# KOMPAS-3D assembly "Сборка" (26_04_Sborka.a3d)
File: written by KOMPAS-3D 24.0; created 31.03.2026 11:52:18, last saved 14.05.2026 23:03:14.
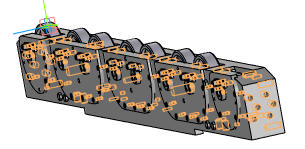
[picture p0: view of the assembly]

Document properties: Автор: taras; Полное имя файла: E:\test_kompas\all_v22\26_04_Sborka.a3d

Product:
- Component [detail]: Деталь  | qty 1  | pos. 2  | Масса: 261.985445; source file: C:\Users\Family\Desktop\kommpas\3.1.8 дет.45 Балка(оригинал) (1).m3d
- Component [detail]: Деталь  | qty 1  | pos. 3  | Масса: 21.934157; Организация: TMK; Автор: TMK; source file: C:\Users\Family\Desktop\kommpas\3.1.8  дет.46.2 Крышка балки (2).m3d
- Component [detail]: Деталь  | qty 1  | pos. 4  | Масса: 21.934157; Организация: TMK; Автор: TMK; source file: C:\Users\Family\Desktop\kommpas\3.1.8  дет.46.2 Крышка балки (2).m3d
- Component [detail]: Деталь  | qty 1  | pos. 5  | Масса: 9.688835; source file: C:\Users\Family\Desktop\kommpas\Крышка балки 1 окончательная (3).m3d
- Component [detail]: Деталь  | qty 1  | pos. 6  | Масса: 2.046242; Организация: TMK; Автор: TMK; source file: C:\Users\Family\Desktop\kommpas\3.1.8 дет.74 Ось кронштейна крепления опорного ролика(новый блок) (1).m3d
- Component [detail]: Деталь  | qty 1  | pos. 7  | Масса: 2.046242; Организация: TMK; Автор: TMK; source file: C:\Users\Family\Desktop\kommpas\3.1.8 дет.74 Ось кронштейна крепления опорного ролика(новый блок) (1).m3d
- Component [detail]: Деталь  | qty 1  | pos. 8  | Масса: 2.046242; Организация: TMK; Автор: TMK; source file: C:\Users\Family\Desktop\kommpas\3.1.8 дет.74 Ось кронштейна крепления опорного ролика(новый блок) (1).m3d
- Component [detail]: Деталь  | qty 1  | pos. 12  | Масса: 19.948382; Автор: taras; source file: C:\Users\Family\Desktop\kommpas\05.04 крышка200.m3d
- Component [detail]: Деталь  | qty 1  | pos. 13  | Масса: 2.046242; Организация: TMK; Автор: TMK; source file: C:\Users\Family\Desktop\kommpas\3.1.8 дет.74 Ось кронштейна крепления опорного ролика(новый блок) (1).m3d
- Component [detail]: Деталь  | qty 1  | pos. 14  | Масса: 2.046242; Организация: TMK; Автор: TMK; source file: C:\Users\Family\Desktop\kommpas\3.1.8 дет.74 Ось кронштейна крепления опорного ролика(новый блок) (1).m3d
- Component [detail]: Деталь  | qty 1  | pos. 15  | Масса: 9.688835; source file: C:\Users\Family\Desktop\kommpas\Крышка балки 1 окончательная (3).m3d
- Component [detail]: Деталь  | qty 1  | pos. 16  | Масса: 2.046242; Организация: TMK; Автор: TMK; source file: C:\Users\Family\Desktop\kommpas\3.1.8 дет.74 Ось кронштейна крепления опорного ролика(новый блок) (1).m3d
- Component [standard]: Винт М10-6gx20 ГОСТ 11738-84  | qty 31  | pos. 17  | Масса: 0.02351; Раздел спецификации: Стандартные изделия; Рассекать на разрезах: no
- Component [detail]: Деталь  | qty 1  | pos. 19  | Масса: 2.046242; Организация: TMK; Автор: TMK; source file: C:\Users\Family\Desktop\kommpas\3.1.8 дет.74 Ось кронштейна крепления опорного ролика(новый блок) (1).m3d
- Component [detail]: Деталь  | qty 1  | pos. 20  | Масса: 2.046242; Организация: TMK; Автор: TMK; source file: C:\Users\Family\Desktop\kommpas\3.1.8 дет.74 Ось кронштейна крепления опорного ролика(новый блок) (1).m3d
- Component [detail]: Деталь  | qty 1  | pos. 21  | Масса: 0.134151; Организация: TMK; Автор: TMK; source file: C:\Users\Family\Desktop\kommpas\Planka_rigelnaya (1).m3d
- Component [detail]: Деталь  | qty 1  | pos. 22  | Масса: 0.134151; Организация: TMK; Автор: TMK; source file: C:\Users\Family\Desktop\kommpas\Planka_rigelnaya (1).m3d
- Component [detail]: Деталь  | qty 1  | pos. 23  | Масса: 0.134151; Организация: TMK; Автор: TMK; source file: C:\Users\Family\Desktop\kommpas\Planka_rigelnaya (1).m3d
- Component [detail]: Деталь  | qty 1  | pos. 24  | Масса: 0.134151; Организация: TMK; Автор: TMK; source file: C:\Users\Family\Desktop\kommpas\Planka_rigelnaya (1).m3d
- Component [detail]: Деталь  | qty 1  | pos. 25  | Масса: 0.134151; Организация: TMK; Автор: TMK; source file: C:\Users\Family\Desktop\kommpas\Planka_rigelnaya (1).m3d
- Component [detail]: Деталь  | qty 1  | pos. 26  | Масса: 0.134151; Организация: TMK; Автор: TMK; source file: C:\Users\Family\Desktop\kommpas\Planka_rigelnaya (1).m3d
- Component [detail]: Деталь  | qty 1  | pos. 27  | Масса: 0.134151; Организация: TMK; Автор: TMK; source file: C:\Users\Family\Desktop\kommpas\Planka_rigelnaya (1).m3d
- Component [detail]: Деталь  | qty 1  | pos. 28  | Масса: 0.134151; Организация: TMK; Автор: TMK; source file: C:\Users\Family\Desktop\kommpas\Planka_rigelnaya (1).m3d
- Component [standard]: Подшипник 318 ГОСТ 8338-75  | qty 7  | pos. 29  | Масса: 4.954; Раздел спецификации: Стандартные изделия; additional columns: 318
- Component [standard]: Болт М16-6gx170 ГОСТ 7795-70  | qty 6  | pos. 30  | Масса: 0.2633; Раздел спецификации: Стандартные изделия; Рассекать на разрезах: no
- Component [standard]: Винт М12-6gx20 ГОСТ 11738-84  | qty 16  | pos. 31  | Масса: 0.03416; Раздел спецификации: Стандартные изделия; Рассекать на разрезах: no
- Part/product: Сборка
    Масса: 400.156123

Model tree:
1. Контекстная связь:2  (with: Грань.Вырезать элемент выдавливания:15, Контекстная связь (Деталь (1)):2, Отверстие:2, Вырезать элемент выдавливания:22, Элемент выдавливания:2, Вырезать элемент выдавливания:16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)  (labels: Скругление:2; Скругление:1; Скругление:2; Скругление:2)
     Ориентация = 2

Referenced files in C:\Users\Family\Desktop\kommpas\: 3.1.8 дет.45 Балка(оригинал) (1).m3d, 3.1.8  дет.46.2 Крышка балки (2).m3d, Крышка балки 1 окончательная (3).m3d, 05.04 крышка200.m3d, 3.1.8 дет.74 Ось кронштейна крепления опорного ролика(новый блок) (1).m3d, Planka_rigelnaya (1).m3d
Referenced files in C:\Users\taras\Downloads\: 3.1.8 дет.74 Ось кронштейна крепления опорного ролика(новый блок) (2).m3d, 3.1.8  дет.46.2 Крышка балки (2).m3d, 3.1.8 дет.74 Ось кронштейна крепления опорного ролика(новый блок) (1).m3d, Крышка балки 1 окончательная (3).m3d, Planka_rigelnaya (1).m3d
Referenced files in C:\Program Files\ASCON\KOMPAS-3D v24\Libs\PolynomLib\DATA\vault\Methods\Kompas\3D\: PLib_Screw_GOST_11738_1500.m3d, PLib_Bolt_1_900.m3d
Referenced files in C:\Program Files\ASCON\KOMPAS-3D v24\Libs\PolynomLib\DATA\vault\Methods\Kompas\3D\Bearings\8338_75\: PLib_Bearing_GOST_8338_75_712.a3d
Referenced files in C:\Program Files\ASCON\KOMPAS-3D v23 Study\Libs\PolynomLib\DATA\vault\Methods\Kompas\3D\: PLib_Screw_GOST_11738_1500.m3d, PLib_Bolt_1_900.m3d
Referenced files in C:\Program Files\ASCON\KOMPAS-3D v23 Study\Libs\PolynomLib\DATA\vault\Methods\Kompas\3D\Bearings\8338_75\: PLib_Bearing_GOST_8338_75_712.a3d
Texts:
  BOSimple***PART:419c87c2-70e2-98da-c2de-5eacb226740c***SHORTLOC:Root±30±20±10±80±10±GMC90[Нет;Без покрытия;Без указания материала;1,5;-;20;10]
  BOSimple***PART:61ab3e34-d848-86f0-c4aa-2b99c9f755c6***SHORTLOC:Root±Pac-16±Pac10±GMC20±GMC30±GMC10±GMC24[90;190;43]
  Крепежное изделие ГОСТ
  BOSimple***PART:9b7fe62b-1d30-3d6e-6be6-01a0e1891a36***SHORTLOC:Root±30±20±10±80±10±©{}30±©{BASE}130±190[Нет;Без покрытия;Без указания материала;170;16;22;2;-]
  BOSimple***PART:d3aa4c40-18a1-862e-ff95-3d42db175957***SHORTLOC:Root±30±20±10±80±10±GMC90[Нет;Без покрытия;Без указания материала;1,75;-;20;12]
  Программные изделия  и базы данных
  Деталь (1)
  Деталь (2)
  Деталь (3)
  Деталь (4)
  Деталь (5)
  Деталь (6)
  Деталь (7)
  Деталь (8)
  Подшипник 318 ГОСТ 8338-75 (1)
  Подшипник 318 ГОСТ 8338-75 (2)
  Подшипник 318 ГОСТ 8338-75 (3)
  Подшипник 318 ГОСТ 8338-75 (4)
  Подшипник 318 ГОСТ 8338-75 (5)
  Подшипник 318 ГОСТ 8338-75 (6)
  Подшипник 318 ГОСТ 8338-75 (7)
  Болт М16-6gx170 ГОСТ 7795-70 (1)
  hole1
  hole2
  Болт М16-6gx170 ГОСТ 7795-70 (2)
  Болт М16-6gx170 ГОСТ 7795-70 (3)
  Болт М16-6gx170 ГОСТ 7795-70 (4)
  Болт М16-6gx170 ГОСТ 7795-70 (5)
  Болт М16-6gx170 ГОСТ 7795-70 (6)
  Радус под головкой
